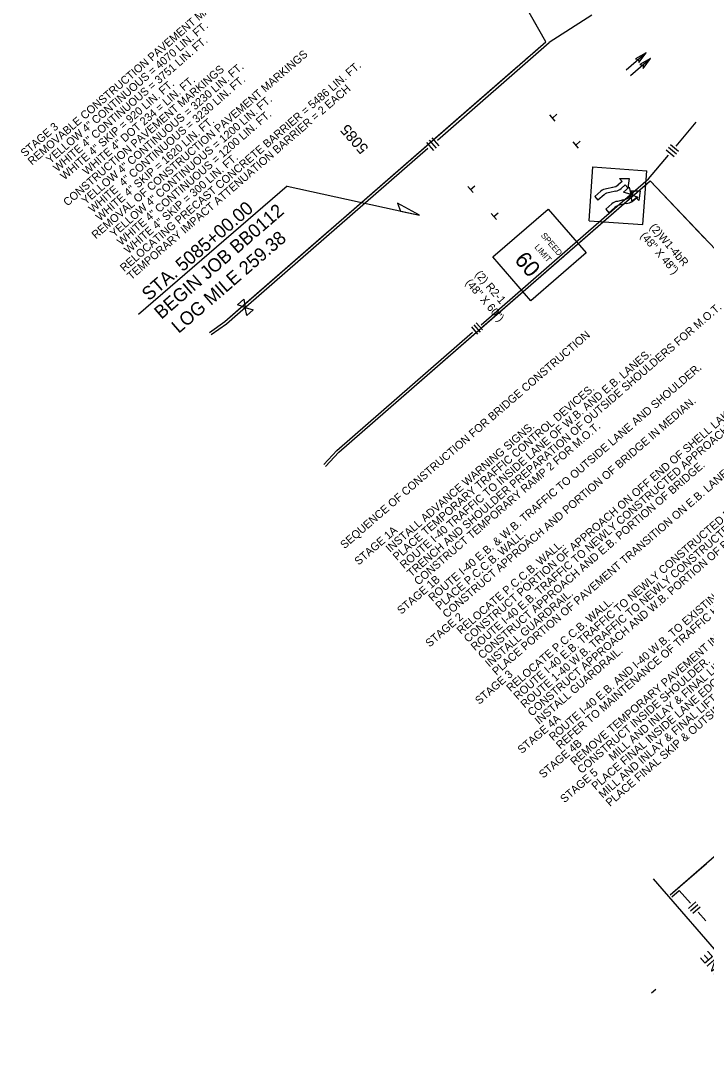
# Model space of a CAD drawing. Extents: x 259983 to 267998, y 211467 to 219827.
# Drawn here: x 262897 to 263924, y 213146 to 214717 of the extents above; entities that cross this region are included whole.
import ezdxf

# ---------------------------------------------------------------- set-up
doc = ezdxf.new("R2010")
doc.units = 0
for name, color, linetype in [('Default', 7, 'Continuous'), ('Level 24', 7, 'Continuous'), ('Level 43', 7, 'Continuous'), ('Level 58', 7, 'Continuous'), ('Level 59', 7, 'Continuous'), ('R-W - CofA', 7, 'Continuous'), ('R_MOT', 7, 'Continuous'), ('R_MOT STAGE 1', 7, 'Continuous'), ('ROAD', 7, 'Continuous'), ('STATIONING1', 7, 'Continuous')]:
    doc.layers.add(name, color=color, linetype=linetype)

msp = doc.modelspace()

# ---------------------------------------------------------------- linework, layer by layer
at = {"layer": 'Level 24'}
for points in [[(263295.6, 214468.8), (263073, 214276.1)], [(263295.6, 214468.8), (263494.3, 214425.1)]]:
    msp.add_lwpolyline(points, dxfattribs=at)
at = {"layer": 'Level 43'}
for points in [[(263834.2, 214668.7), (263804.1, 214642.8)], [(263840.7, 214660), (263810.7, 214634)]]:
    msp.add_lwpolyline(points, dxfattribs=at)
at = {"layer": 'Level 58'}
for points in [[(263823, 214654.1), (263834.2, 214668.7), (263818.1, 214659.8), (263822.8, 214658.9)], [(263829.6, 214645.4), (263840.7, 214660), (263824.7, 214651.1), (263829.4, 214650.2)]]:
    msp.add_lwpolyline(points, close=True, dxfattribs=at)
at = {"layer": 'Level 59'}
msp.add_lwpolyline([(263465.6, 214431.4), (263494.3, 214425.1), (263461.1, 214443.2)], close=True, dxfattribs=at)
at = {"layer": 'R-W - CofA'}
for p, q in [((263512.8, 214541.1), (263523, 214529.4)), ((263504.9, 214534.3), (263515.2, 214522.5)), ((263508.9, 214537.7), (263519.1, 214526)), ((263867.4, 214527.2), (263879.4, 214517.1)), ((263870.8, 214531.2), (263882.7, 214521.1)), ((263864.1, 214523.2), (263876, 214513.1)), ((263800.3, 214459.8), (263808.7, 214467.2)), ((263808.7, 214467.2), (263810.9, 214456.2)), ((263810.9, 214456.2), (263800.3, 214459.8)), ((263813, 214445.1), (263810.9, 214456.2)), ((263810.9, 214456.2), (263821.5, 214452.5)), ((263821.5, 214452.5), (263813, 214445.1)), ((263221.4, 214291), (263230.7, 214299.1)), ((263233, 214287), (263221.4, 214291)), ((263230.7, 214299.1), (263233, 214287)), ((263235.4, 214275), (263233, 214287)), ((263233, 214287), (263244.6, 214283.1)), ((263244.6, 214283.1), (263235.4, 214275)), ((263572, 214257.6), (263581.4, 214246.8)), ((263575.6, 214260.7), (263585, 214249.9)), ((263579.2, 214263.9), (263588.6, 214253.1)), ((263883.8, 213412.7), (263900.6, 213393.4)), ((263897.5, 213385.8), (263908.6, 213395.4)), ((263900.7, 213382.1), (263911.8, 213391.7)), ((263903.9, 213378.4), (263915, 213388)), ((263912, 213380.3), (263923.5, 213367.1))]:
    msp.add_line(p, q, dxfattribs=at)
for points in [[(263683.6, 214685.1), (263510.6, 214990.5)], [(263663.7, 214667.8), (263683.6, 214685.1), (263612.6, 214810.5)], [(263752.6, 214725.2), (263688.9, 214684.2)], [(263179.3, 214249.4), (263202.3, 214265.7), (263683.6, 214685.1)], [(263521, 214538), (263688.9, 214684.2)], [(263518.3, 214541.1), (263642.2, 214649.1)], [(263646.2, 214652.5), (263651, 214656.7)], [(263654.9, 214660.2), (263659.7, 214664.3)], [(263879, 214528.8), (263909.2, 214564.7)], [(263237.7, 214291.1), (263506.9, 214525.7)], [(263380.3, 214420.9), (263504.2, 214528.8)], [(263837.7, 214479.6), (263867.6, 214515.2)], [(263353.2, 214048.5), (263373.1, 214069.7), (263840.2, 214476.7)], [(263586.8, 214261), (263837.7, 214479.6)], [(263722.5, 214374.2), (263840.2, 214476.7)], [(263840.2, 214476.7), (263921.7, 214390.9)], [(263840.2, 214476.7), (264006.8, 214301.3)], [(263371.6, 214413.2), (263376.3, 214417.4)], [(263234.9, 214294.2), (263358.8, 214402.1)], [(263362.8, 214405.6), (263367.6, 214409.8)], [(263714.4, 214367.2), (263718.8, 214371)], [(263589.3, 214258.1), (263702.8, 214357)], [(263706.4, 214360.2), (263710.8, 214364)], [(263179.3, 214249.4), (263202.3, 214265.7), (263234.9, 214294.2)], [(263182, 214246.3), (263204.8, 214262.5), (263237.7, 214291.1)], [(263350.7, 214051.4), (263370.4, 214072.5), (263573.8, 214249.7)], [(263462.9, 214147.9), (263576.3, 214246.8)], [(263353.2, 214048.5), (263373.1, 214069.7), (263443.2, 214130.8)], [(263446.8, 214134), (263451.2, 214137.8)], [(263454.8, 214141), (263459.2, 214144.8)], [(263870.1, 213406), (264355.5, 213829)], [(263870.1, 213406), (263924.4, 213453.3)], [(263872.6, 213403), (263883.8, 213412.7)]]:
    msp.add_lwpolyline(points, dxfattribs=at)
at = {"layer": 'R_MOT'}
for p, q in [((263697.7, 214566.4), (263689.7, 214575.7)), ((263693.7, 214571), (263700.2, 214576.6)), ((263732.8, 214525.9), (263724.8, 214535.2)), ((263728.8, 214530.5), (263735.3, 214536.1)), ((263748.5, 214417), (263754.3, 214497.8)), ((263754.3, 214497.8), (263835.1, 214492)), ((263829.3, 214411.2), (263835.1, 214492)), ((263794.2, 214480.5), (263798.1, 214476)), ((263794.2, 214480.5), (263808.8, 214480.5)), ((263808.8, 214480.5), (263806.6, 214466.1)), ((263574.8, 214459.2), (263566.7, 214468.5)), ((263570.8, 214463.8), (263577.2, 214469.4)), ((263766.2, 214461.1), (263757.1, 214453.2)), ((263783.9, 214467), (263774.8, 214464.8)), ((263788, 214461.5), (263779.5, 214459.4)), ((263798.1, 214476), (263792.3, 214471)), ((263802.7, 214470.6), (263796.6, 214465.2)), ((263802.7, 214470.6), (263806.6, 214466.1)), ((263810.5, 214461.6), (263825.1, 214461.7)), ((263810.5, 214461.6), (263814.4, 214457.1)), ((263825.1, 214461.7), (263822.9, 214447.2)), ((263757.1, 214453.2), (263761.7, 214447.8)), ((263770.9, 214455.7), (263761.7, 214447.8)), ((263800.2, 214448.1), (263791.1, 214446)), ((263814.4, 214457.1), (263808.7, 214452.1)), ((263819.1, 214451.7), (263812.9, 214446.4)), ((263819.1, 214451.7), (263822.9, 214447.2)), ((263782.5, 214442.3), (263773.4, 214434.4)), ((263773.4, 214434.4), (263778.1, 214429)), ((263787.2, 214436.9), (263778.1, 214429)), ((263804.3, 214442.6), (263795.8, 214440.6)), ((263609.8, 214418.7), (263601.8, 214428)), ((263605.8, 214423.3), (263612.3, 214428.9)), ((263748.5, 214417), (263829.3, 214411.2))]:
    msp.add_line(p, q, dxfattribs=at)
msp.add_lwpolyline([(263743.9, 214368.6), (263661.1, 214296.9), (263604.2, 214362.6), (263687.1, 214434.3)], close=True, dxfattribs=at)
for centre, major_axis in [((263778.1, 214448), (-11.6, 13.4)), ((263780.5, 214484.2), (11.6, -13.4)), ((263784.7, 214478.4), (11.6, -13.4)), ((263782.8, 214442.5), (-11.6, 13.4)), ((263794.4, 214429.1), (-11.6, 13.4)), ((263796.8, 214465.3), (11.6, -13.4)), ((263801, 214459.6), (11.6, -13.4)), ((263799.1, 214423.7), (-11.6, 13.4))]:
    msp.add_ellipse(centre, major_axis=major_axis, ratio=0.9, start_param=5.717125, end_param=6.306311, dxfattribs=at)
at = {"layer": 'R_MOT STAGE 1'}
msp.add_line((264090.9, 213146.3), (263845.2, 213430.2), dxfattribs=at)
at = {"layer": 'ROAD'}
msp.add_line((263842, 213259.1), (263848.4, 213264.8), dxfattribs=at)

# ---------------------------------------------------------------- texts
at = {"layer": 'Default'}
for s, p in [('REMOVABLE CONSTRUCTION PAVEMENT MARKINGS', (262913.2, 214499.6)), ('     YELLOW 4" CONTINUOUS = 4070 LIN. FT.', (262923.8, 214487.3)), ('     WHITE 4" CONTINUOUS = 3751 LIN. FT.', (262934.5, 214475)), ('REMOVAL OF CONSTRUCTION PAVEMENT MARKINGS', (263008.9, 214389)), ('CONSTRUCTION PAVEMENT MARKINGS', (262966.4, 214438.1)), ('     YELLOW 4" CONTINUOUS = 3230 LIN. FT.', (262977, 214425.8)), ('RELOCATING PRECAST CONCRETE BARRIER = 5486 LIN. FT.', (263051.5, 214339.8)), ('     WHITE 4" SKIP = 920 LIN. FT.', (262945.1, 214462.7)), (' WHITE 4" DOT 234 = LIN. FT.', (262992, 214481.8)), ('     WHITE  4" CONTINUOUS = 3230 LIN. FT.', (262987.6, 214413.5)), ('TEMPORARY IMPACT ATTENUATION BARRIER = 2 EACH', (263062.1, 214327.5)), ('     YELLOW 4" CONTINUOUS = 1200 LIN. FT.', (263019.6, 214376.7)), ('     WHITE 4" SKIP = 1620 LIN. FT.', (262998.3, 214401.2)), ('     WHITE 4" CONTINUOUS = 1200 LIN. FT.', (263030.2, 214364.4)), ('STAGE 3', (262902.5, 214511.9)), ('     WHITE 4" SKIP = 300 LIN. FT.', (263040.8, 214352.1))]:
    msp.add_text(s, height=12, rotation=40.8833, dxfattribs=at).set_placement(p)
at = {"layer": 'Level 24'}
for s, p in [('STA. 5085+00.00', (263088.6, 214295.9)), ('BEGIN JOB BB0112', (263107.2, 214268.3)), ('LOG MILE 259.38', (263133.1, 214247.1))]:
    msp.add_text(s, height=20, rotation=40.8833, dxfattribs=at).set_placement(p)
at = {"layer": 'R_MOT'}
for s, height, rotation, p in [('SPEED', 9.05, 310.8555, (263675.6, 214394.5)), ('(48" X 48")', 12, 310.8833, (263824.5, 214394)), ('(2)W1-4bR', 12, 310.8833, (263838.5, 214406.8)), ('LIMIT', 9.05, 310.8555, (263666, 214377)), ('60', 24.26, 310.8555, (263635.4, 214357.5)), ('(2) R2-1', 12.13, 310.8555, (263576.7, 214336)), ('(48" X 60")', 12.129, 310.8555, (263562.2, 214323.5))]:
    msp.add_text(s, height=height, rotation=rotation, dxfattribs=at).set_placement(p)
at = {"layer": 'ROAD'}
for s, p in [('CONSTRUCT PORTION OF APPROACH ON OFF END OF SHELL LAKE BRIDGE PRIOR TO SHIFTING OF TRAFFIC.', (263567, 213783.7)), ('TRENCH AND SHOULDER PREPARATION OF OUTSIDE SHOULDERS FOR M.O.T.', (263481.9, 213882)), ('SEQUENCE OF CONSTRUCTION FOR BRIDGE CONSTRUCTION', (263381.8, 213924.3)), ('ROUTE I-40 E.B. TRAFFIC TO NEWLY CONSTRUCTED APPROACH AND BRIDGE IN MEDIAN.', (263577.6, 213771.4)), ('PLACE PORTION OF PAVEMENT TRANSITION ON E.B. LANES UTILIZING ONE LANE OF TRAFFIC.', (263609.6, 213734.5)), ('ROUTE I-40 TRAFFIC TO INSIDE LANE OF W.B. AND E.B. LANES.', (263471.2, 213894.3)), ('ROUTE I-40 E.B. & W.B. TRAFFIC TO OUTSIDE LANE AND SHOULDER.', (263513.8, 213845.1)), ('PLACE TEMPORARY TRAFFIC CONTROL DEVICES.', (263460.6, 213906.6)), ('CONSTRUCT APPROACH AND PORTION OF BRIDGE IN MEDIAN.', (263535.1, 213820.6)), ('ROUTE I-40 E.B. TRAFFIC TO NEWLY CONSTRUCTED BRIDGE AND EXISTING E.B. LANES.', (263641.5, 213697.7)), ('ROUTE 1-40 W.B. TRAFFIC TO NEWLY CONSTRUCTED APPROACH AND BRIDGE IN MEDIAN.', (263652.1, 213685.4)), ('REFER TO MAINTENANCE OF TRAFFIC HWY. 149 INTERCHANGE RAMP RECONSTRUCTION SHEETS.', (263705.3, 213623.9)), ('INSTALL ADVANCE WARNING SIGNS.', (263450, 213918.9)), ('CONSTRUCT TEMPORARY RAMP 2 FOR M.O.T.', (263492.5, 213869.7)), ('CONSTRUCT APPROACH AND E.B. PORTION OF BRIDGE.', (263588.3, 213759.1)), ('CONSTRUCT APPROACH AND W.B. PORTION OF BRIDGE.', (263662.7, 213673.1)), ('STAGE 1A', (263403, 213899.7)), ('PLACE P.C.C.B. WALL.', (263524.4, 213832.8)), ('RELOCATE P.C.C.B. WALL.', (263556.4, 213796)), ('ROUTE I-40 E.B. AND I-40 W.B. TO EXISTING LANES.', (263694.7, 213636.2)), ('STAGE 1B', (263466.9, 213826)), ('INSTALL GUARDRAIL.', (263598.9, 213746.8)), ('MILL AND INLAY & FINAL LIFT OF INSIDE LANES.', (263784.1, 213606.2)), ('RELOCATE P.C.C.B. WALL.', (263630.8, 213709.9)), ('REMOVE TEMPORARY PAVEMENT IN MEDIAN.', (263726.6, 213599.3)), ('STAGE 2', (263509.4, 213776.8)), ('MILL AND INLAY & FINAL LIFT OF OUTSIDE LANES.', (263769.1, 213550.2)), ('PLACE FINAL SKIP & OUTSIDE LANE EDGE STRIPING.', (263779.8, 213537.9)), ('PLACE FINAL INSIDE LANE EDGE STRIPING.', (263758.5, 213562.5)), ('INSTALL GUARDRAIL.', (263673.4, 213660.8)), ('CONSTRUCT INSIDE SHOULDER.', (263737.2, 213587.1)), ('STAGE 3', (263583.9, 213690.8)), ('STAGE 4A', (263647.7, 213617.1)), ('STAGE 4B', (263679.7, 213580.2)), ('STAGE 5', (263711.6, 213543.3))]:
    msp.add_text(s, height=12, rotation=40.8833, dxfattribs=at).set_placement(p)
at = {"layer": 'STATIONING1'}
for s, p in [('5085', (263418.7, 214526.1)), ('MATCH LINE', (264013.7, 213222))]:
    msp.add_text(s, height=16.5, rotation=130.8833, dxfattribs=at).set_placement(p)

doc.saveas('drawing.dxf')
